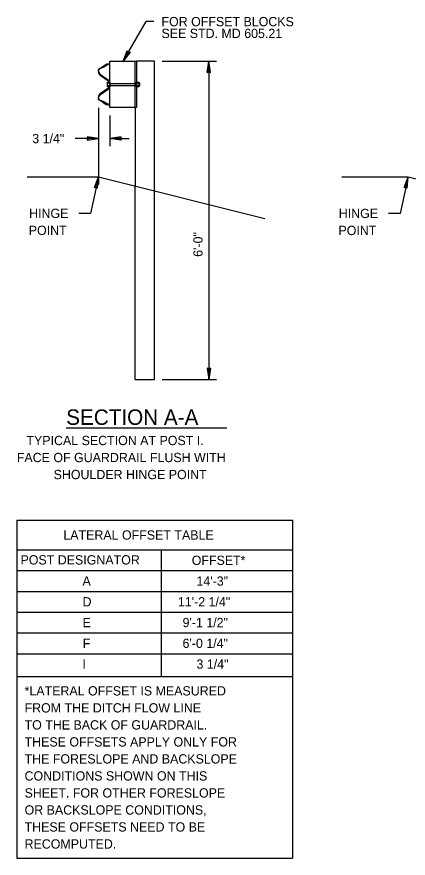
# Model space of a CAD drawing. Extents: x 12.4 to 19.6, y 6 to 16.
# Drawn here: x 12.68 to 15.21, y 10.6 to 16.04 of the extents above; entities that cross this region are included whole.
import ezdxf

# ---------------------------------------------------------------- set-up
doc = ezdxf.new("R2010")
doc.units = 0
for name, color, linetype in [('DETL-DIMS', 7, 'Continuous'), ('DETL-LINE', 7, 'Continuous'), ('DETL-NOTE', 7, 'Continuous'), ('DETL-TITL', 7, 'Continuous')]:
    doc.layers.add(name, color=color, linetype=linetype)

msp = doc.modelspace()

# ---------------------------------------------------------------- linework, layer by layer
at = {"layer": 'DETL-DIMS'}
for p, q in [((13.3685, 15.7512), (13.5165, 16.0075)), ((13.5665, 16.0075), (13.5165, 16.0075)), ((13.3957, 15.8195), (13.3685, 15.7512)), ((13.4141, 15.8089), (13.3685, 15.7512)), ((13.3957, 15.8195), (13.4003, 15.8064)), ((13.4141, 15.8089), (13.4003, 15.8064)), ((13.6218, 15.7512), (13.9725, 15.7512)), ((13.9119, 15.6784), (13.9225, 15.7512)), ((13.9225, 15.7512), (13.9225, 13.6937)), ((13.9331, 15.6784), (13.9225, 15.7512)), ((13.9119, 15.6784), (13.9225, 15.6875)), ((13.9331, 15.6784), (13.9225, 15.6875)), ((13.2085, 15.4495), (13.2085, 14.9537)), ((13.2827, 15.4012), (13.2827, 15.2012)), ((13.2085, 15.2512), (13.0585, 15.2512)), ((13.1357, 15.2618), (13.2085, 15.2512)), ((13.1357, 15.2618), (13.1448, 15.2512)), ((13.1357, 15.2406), (13.2085, 15.2512)), ((13.1357, 15.2406), (13.1448, 15.2512)), ((13.3555, 15.2618), (13.2827, 15.2512)), ((13.3555, 15.2406), (13.2827, 15.2512)), ((13.2827, 15.2512), (13.4077, 15.2512)), ((13.3555, 15.2618), (13.3464, 15.2512)), ((13.3555, 15.2406), (13.3464, 15.2512)), ((13.2085, 15.0037), (13.1568, 14.7674)), ((13.1826, 14.9347), (13.2085, 15.0037)), ((13.2033, 14.9302), (13.2085, 15.0037)), ((15.2107, 15.0033), (15.159, 14.767)), ((15.1848, 14.9343), (15.2107, 15.0033)), ((15.2055, 14.9298), (15.2107, 15.0033)), ((13.1826, 14.9347), (13.1949, 14.9414)), ((13.2033, 14.9302), (13.1949, 14.9414)), ((15.1848, 14.9343), (15.1971, 14.9409)), ((15.2055, 14.9298), (15.1971, 14.9409)), ((13.1568, 14.7674), (13.0818, 14.7674)), ((15.159, 14.767), (15.084, 14.767)), ((13.9119, 13.7665), (13.9225, 13.6937)), ((13.9119, 13.7665), (13.9225, 13.7574)), ((13.9331, 13.7665), (13.9225, 13.6937)), ((13.9331, 13.7665), (13.9225, 13.7574)), ((13.6218, 13.6937), (13.9725, 13.6937)), ((12.6813, 12.7837), (14.4627, 12.7837)), ((12.6813, 12.7837), (12.6813, 10.5977)), ((14.4627, 12.7837), (14.4627, 10.5977)), ((12.6813, 12.5912), (14.4627, 12.5912)), ((13.6163, 11.7718), (13.6163, 12.5912)), ((12.6813, 12.457), (14.4627, 12.457)), ((12.6813, 12.3228), (14.4627, 12.3228)), ((12.6813, 12.1885), (14.4627, 12.1885)), ((12.6813, 12.0543), (14.4627, 12.0543)), ((12.6813, 11.9201), (14.4627, 11.9201)), ((12.6813, 11.7718), (14.4627, 11.7718)), ((12.6813, 10.5977), (14.4627, 10.5977))]:
    msp.add_line(p, q, dxfattribs=at)
for points in [[(13.4141, 15.8089), (13.3685, 15.7512), (13.3957, 15.8195), (13.4003, 15.8064)], [(13.9331, 15.6784), (13.9225, 15.7512), (13.9119, 15.6784), (13.9225, 15.6875)], [(13.1357, 15.2406), (13.2085, 15.2512), (13.1357, 15.2618), (13.1448, 15.2512)], [(13.3555, 15.2406), (13.2827, 15.2512), (13.3555, 15.2618), (13.3464, 15.2512)], [(13.2033, 14.9302), (13.2085, 15.0037), (13.1826, 14.9347), (13.1949, 14.9414)], [(15.2055, 14.9298), (15.2107, 15.0033), (15.1848, 14.9343), (15.1971, 14.9409)], [(13.9119, 13.7665), (13.9225, 13.6937), (13.9331, 13.7665), (13.9225, 13.7574)]]:
    msp.add_lwpolyline(points, close=True, dxfattribs=at)
at = {"layer": 'DETL-LINE'}
for p, q in [((13.446, 15.4512), (13.446, 15.7512)), ((13.2672, 15.6166), (13.2827, 15.6166)), ((13.2672, 15.5858), (13.2672, 15.6166)), ((13.2827, 15.6166), (13.2827, 15.5858)), ((13.4543, 15.6166), (13.4698, 15.6166)), ((13.4543, 15.5858), (13.4543, 15.6166)), ((13.4698, 15.6166), (13.4698, 15.5858)), ((13.2827, 15.6089), (13.2672, 15.6089)), ((13.2672, 15.5935), (13.2827, 15.5935)), ((13.2827, 15.5858), (13.2672, 15.5858)), ((13.2827, 15.6079), (13.4543, 15.6079)), ((13.2827, 15.5945), (13.4543, 15.5945)), ((13.4698, 15.6089), (13.4543, 15.6089)), ((13.4543, 15.5935), (13.4698, 15.5935)), ((13.4698, 15.5858), (13.4543, 15.5858)), ((13.4775, 15.6089), (13.4698, 15.6089)), ((13.4698, 15.5935), (13.4775, 15.5935)), ((13.4775, 15.5935), (13.4775, 15.6089)), ((13.446, 13.6937), (13.446, 14.9443)), ((13.5718, 13.6937), (13.5718, 14.9128)), ((13.446, 13.6937), (13.5718, 13.6937))]:
    msp.add_line(p, q, dxfattribs=at)
for points in [[(13.2802, 15.7345), (13.2635, 15.732), (13.2585, 15.7295), (13.2193, 15.7037), (13.216, 15.7012), (13.2135, 15.6979), (13.211, 15.6945), (13.2093, 15.6912)], [(13.2827, 15.7295), (13.2652, 15.727)], [(13.2827, 15.7354), (13.2802, 15.7345)], [(13.5718, 14.9129), (13.5718, 15.7512), (13.5677, 15.7512), (13.461, 15.7512), (13.4543, 15.7512)], [(13.2093, 15.6912), (13.2085, 15.687), (13.2085, 15.6787), (13.2093, 15.6745)], [(13.2093, 15.6745), (13.211, 15.6712), (13.216, 15.6645), (13.2193, 15.662), (13.2693, 15.627), (13.2727, 15.6237), (13.2743, 15.6212), (13.2752, 15.6195)], [(13.2227, 15.6662), (13.2727, 15.6312), (13.276, 15.6287), (13.2785, 15.6254), (13.281, 15.6212), (13.2819, 15.6166)], [(13.2762, 15.6166), (13.276, 15.617), (13.2752, 15.6195)], [(13.276, 15.5858), (13.276, 15.5845), (13.2752, 15.5812), (13.2735, 15.5787), (13.2693, 15.5745), (13.2193, 15.5404), (13.216, 15.5379), (13.2135, 15.5345), (13.211, 15.5312), (13.2093, 15.527)], [(13.2227, 15.5362), (13.2727, 15.5704), (13.276, 15.5737), (13.281, 15.5804), (13.2821, 15.5858)], [(13.2827, 15.6129), (13.2827, 15.6079)], [(13.2827, 15.5887), (13.2827, 15.5945)], [(13.2093, 15.527), (13.2085, 15.5237), (13.2085, 15.5154), (13.2093, 15.5112)], [(13.2093, 15.5112), (13.211, 15.5079), (13.2135, 15.5037), (13.216, 15.5012), (13.2193, 15.4987), (13.2585, 15.472), (13.2602, 15.4712), (13.2618, 15.4704), (13.2635, 15.4704), (13.2802, 15.467)], [(13.2827, 15.4729), (13.2652, 15.4754), (13.2643, 15.4754)], [(13.2802, 15.467), (13.2827, 15.467)], [(13.446, 15.4512), (13.446, 14.9445)], [(12.7476, 15.0037), (13.2085, 15.0037), (14.2849, 14.7345)], [(14.7828, 15.0033), (15.2107, 15.0033), (16.754, 14.6174)]]:
    msp.add_lwpolyline(points, dxfattribs=at)
msp.add_lwpolyline([(13.2827, 15.4512), (13.2827, 15.7512), (13.4543, 15.7512), (13.4543, 15.4512)], close=True, dxfattribs=at)
for points in [[(13.2652, 15.727), (13.2479, 15.7138), (13.193, 15.6951), (13.2227, 15.6662)], [(13.2227, 15.5362), (13.1925, 15.5045), (13.2488, 15.4921), (13.2643, 15.4754)]]:
    msp.add_open_spline(points, degree=2, dxfattribs=at)
at = {"layer": 'DETL-TITL'}
msp.add_line((13.0005, 13.3814), (14.0392, 13.3814), dxfattribs=at)

# ---------------------------------------------------------------- texts
at = {"layer": 'DETL-NOTE'}
for s, rotation, p in [('FOR OFFSET BLOCKS', 360, (13.6165, 15.9775)), ('SEE STD. MD 605.21', 360, (13.6165, 15.9012)), ('3 1/4"', 360, (12.7812, 15.2212)), ('HINGE', 360, (12.7606, 14.7374)), ('HINGE', 360, (14.7628, 14.737)), ('POINT', 360, (12.7585, 14.6274)), ('6\'-0"', 90, (13.8825, 14.4863)), ('POINT', 360, (14.7607, 14.627)), ('TYPICAL SECTION AT POST I.', 360, (12.7435, 13.2687)), ('FACE OF GUARDRAIL FLUSH WITH', 360, (12.6813, 13.1587)), ('SHOULDER HINGE POINT', 360, (12.9192, 13.0487)), ('LATERAL OFFSET TABLE', 360, (12.9822, 12.6575)), ('POST DESIGNATOR', 360, (12.7052, 12.4968)), ('OFFSET*', 360, (13.8123, 12.4941)), ('A', 360, (13.1058, 12.3599)), ('14\'-3"', 360, (13.8428, 12.3599)), ('D', 360, (13.1065, 12.2256)), ('11\'-2 1/4"', 360, (13.7228, 12.2256)), ('E', 360, (13.1068, 12.0914)), ('9\'-1 1/2"', 360, (13.7528, 12.0914)), ('F', 360, (13.1079, 11.9572)), ('6\'-0 1/4"', 360, (13.7528, 11.9572)), ('I', 360, (13.1058, 11.8229)), ('3 1/4"', 360, (13.8428, 11.8229)), ('*LATERAL OFFSET IS MEASURED', 360, (12.7313, 11.6497)), ('FROM THE DITCH FLOW LINE', 360, (12.7313, 11.5397)), ('TO THE BACK OF GUARDRAIL.', 360, (12.7313, 11.4297)), ('THESE OFFSETS APPLY ONLY FOR', 360, (12.7313, 11.3197)), ('THE FORESLOPE AND BACKSLOPE', 360, (12.7313, 11.2097)), ('CONDITIONS SHOWN ON THIS', 360, (12.7313, 11.0997)), ('SHEET. FOR OTHER FORESLOPE', 360, (12.7313, 10.9897)), ('OR BACKSLOPE CONDITIONS,', 360, (12.7313, 10.8797)), ('THESE OFFSETS NEED TO BE', 360, (12.7313, 10.7697)), ('RECOMPUTED.', 360, (12.7313, 10.6597))]:
    msp.add_text(s, height=0.06, rotation=rotation, dxfattribs=at).set_placement(p)
at = {"layer": 'DETL-TITL'}
msp.add_text('SECTION A-A', height=0.1, rotation=360, dxfattribs=at).set_placement((13.0005, 13.3997))

doc.saveas('drawing.dxf')
